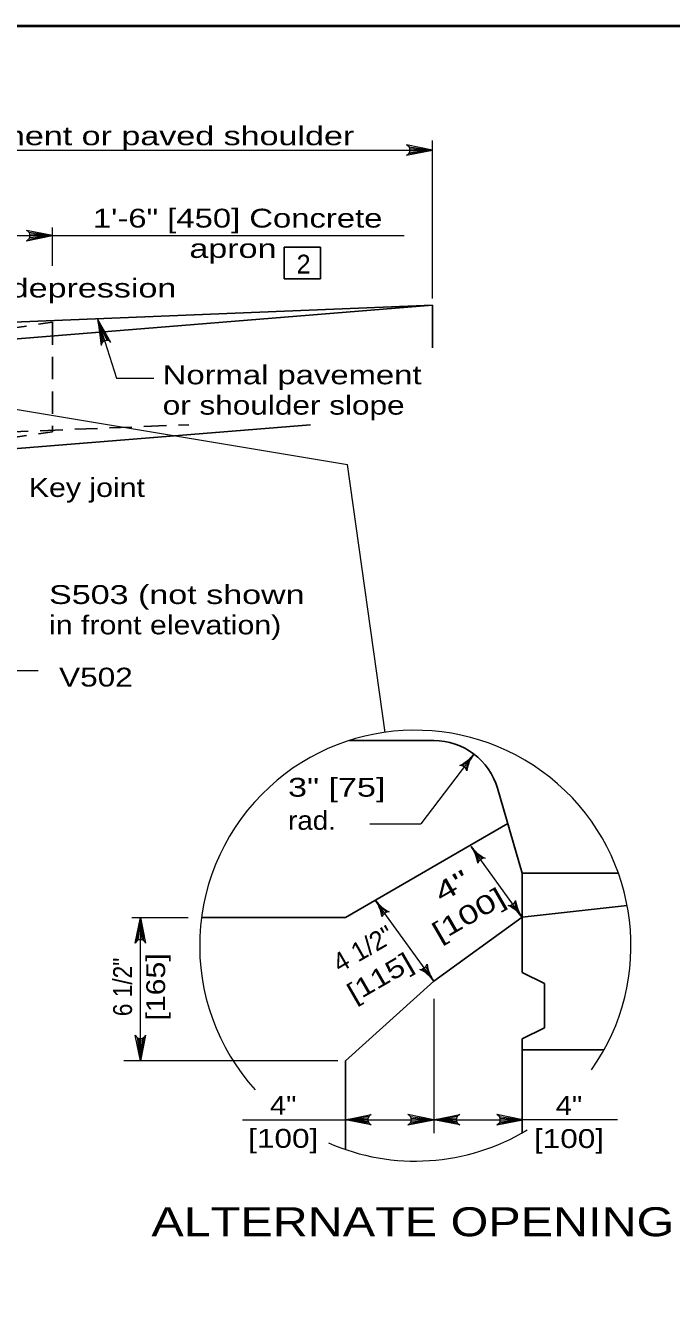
# Model space of a CAD drawing. Extents: x 758.3 to 792.3, y 849.7 to 893.7.
# Drawn here: x 770.01 to 775.35, y 860.56 to 871.19 of the extents above; entities that cross this region are included whole.
import ezdxf
from ezdxf.enums import TextEntityAlignment as Align

# ---------------------------------------------------------------- set-up
doc = ezdxf.new("R2010")
doc.units = 0
doc.header["$LTSCALE"] = 0.062
doc.linetypes.add('MEDIUM_DASHED', pattern=[4.5, 3, -1.5])
doc.layers.add('1', color=7, linetype='Continuous', lineweight=13)

msp = doc.modelspace()

# ---------------------------------------------------------------- linework, layer by layer
at = {"layer": '1', "lineweight": 25}
for p, q in [((760.3205, 871.18817), (791.8205, 871.18817)), ((768.41517, 868.47117), (773.37233, 868.87425)), ((768.6345, 868.68158), (773.37233, 868.87425)), ((773.37233, 868.87425), (773.37233, 868.52192)), ((768.41517, 867.56425), (772.36417, 867.88542)), ((772.6855, 865.271), (773.38417, 865.271)), ((774.11583, 864.17358), (773.911, 864.87592)), ((772.65242, 863.80775), (773.9965, 864.58367)), ((774.98375, 863.90433), (774.11583, 863.80792)), ((771.46317, 863.80775), (772.65242, 863.80775)), ((774.11583, 863.35067), (774.29875, 863.25917)), ((774.29875, 862.89333), (774.29875, 863.25917)), ((774.11583, 862.80192), (774.29875, 862.89333)), ((774.11583, 862.02475), (774.11583, 862.80192)), ((774.79217, 862.7105), (774.11517, 862.7105)), ((772.65242, 861.88642), (772.65242, 862.61875))]:
    msp.add_line(p, q, dxfattribs=at)
at = {"layer": '1'}
for p, q in [((773.37233, 868.92917), (773.37233, 870.23767)), ((768.41517, 870.159), (773.37233, 870.159)), ((773.17608, 870.129), (773.37233, 870.159)), ((773.17842, 870.18608), (773.37233, 870.159)), ((773.1835, 870.14158), (773.37233, 870.159)), ((773.185, 870.17267), (773.37233, 870.159)), ((773.187, 870.159), (773.37233, 870.159)), ((768.41517, 869.451), (773.1385, 869.451)), ((770.03317, 869.421), (770.22933, 869.451)), ((770.03542, 869.47808), (770.22933, 869.451)), ((770.04058, 869.43358), (770.22933, 869.451)), ((770.042, 869.46467), (770.22933, 869.451)), ((770.044, 869.451), (770.22933, 869.451)), ((770.22933, 869.19967), (770.22933, 869.51842)), ((770.66417, 868.58058), (770.60517, 868.75625)), ((770.68183, 868.58292), (770.60517, 868.75625)), ((770.69608, 868.57983), (770.60517, 868.75625)), ((770.65183, 868.57433), (770.60517, 868.75625)), ((770.64125, 868.56383), (770.60517, 868.75625)), ((768.71325, 868.21517), (772.67008, 867.555)), ((772.9825, 865.33825), (772.67008, 867.555)), ((769.69142, 865.85208), (770.11175, 865.85208)), ((773.71558, 865.15958), (773.27658, 864.58075)), ((772.85533, 864.58075), (773.27658, 864.58075)), ((774.11583, 863.80792), (773.69208, 864.39492)), ((773.38417, 863.27983), (772.89992, 863.95067)), ((770.88533, 863.80775), (771.35192, 863.80775)), ((770.92783, 863.61158), (770.95775, 863.80775)), ((770.94033, 863.619), (770.95775, 863.80775)), ((770.95775, 862.61875), (770.95775, 863.80775)), ((770.95775, 863.62242), (770.95775, 863.80775)), ((770.9715, 863.62042), (770.95775, 863.80775)), ((770.98492, 863.61392), (770.95775, 863.80775)), ((773.38417, 863.13433), (773.38417, 862.02175)), ((770.93067, 862.81267), (770.95775, 862.61875)), ((770.94408, 862.80608), (770.95775, 862.61875)), ((770.98775, 862.81492), (770.95775, 862.61875)), ((770.97517, 862.8075), (770.95775, 862.61875)), ((770.95775, 862.80408), (770.95775, 862.61875)), ((772.591, 862.61875), (770.8205, 862.61875)), ((771.803, 862.13292), (773.16875, 862.13292)), ((772.84633, 862.16008), (772.65242, 862.13292)), ((772.83975, 862.14667), (772.65242, 862.13292)), ((772.83775, 862.13292), (772.65242, 862.13292)), ((772.84117, 862.1155), (772.65242, 862.13292)), ((772.84867, 862.10292), (772.65242, 862.13292)), ((773.188, 862.10292), (773.38417, 862.13292)), ((773.19025, 862.16008), (773.38417, 862.13292)), ((773.19542, 862.1155), (773.38417, 862.13292)), ((773.19683, 862.14667), (773.38417, 862.13292)), ((773.19883, 862.13292), (773.38417, 862.13292)), ((773.57808, 862.16008), (773.38417, 862.13292)), ((773.5715, 862.14667), (773.38417, 862.13292)), ((773.5695, 862.13292), (773.38417, 862.13292)), ((773.57292, 862.1155), (773.38417, 862.13292)), ((773.58033, 862.10292), (773.38417, 862.13292)), ((773.92325, 862.10292), (774.11942, 862.13292)), ((773.9255, 862.16008), (774.11942, 862.13292)), ((773.93067, 862.1155), (774.11942, 862.13292)), ((773.93208, 862.14667), (774.11942, 862.13292)), ((773.93408, 862.13292), (774.11942, 862.13292)), ((774.90317, 862.13292), (774.11942, 862.13292))]:
    msp.add_line(p, q, dxfattribs=at)
at = {"layer": '1', "linetype": 'MEDIUM_DASHED', "lineweight": 25}
for p, q in [((768.41517, 868.47117), (770.22933, 868.73317)), ((770.22933, 868.73317), (770.22933, 867.82625)), ((768.41517, 867.76575), (771.35858, 867.88542)), ((768.41517, 867.56425), (770.22933, 867.82625))]:
    msp.add_line(p, q, dxfattribs=at)
at = {"layer": '1', "lineweight": 40}
msp.add_lwpolyline([(760.3205, 871.18817), (791.8205, 871.18817), (791.8205, 850.18817), (760.3205, 850.18817)], close=True, dxfattribs=at)
at = {"layer": '1'}
for points in [[(773.15817, 870.11617), (773.37233, 870.159), (773.15817, 870.20183)], [(770.01517, 869.40817), (770.22933, 869.451), (770.01517, 869.49383)], [(770.714, 868.56692), (770.60517, 868.75625), (770.63275, 868.53958)], [(770.60517, 868.75625), (770.76075, 868.27), (771.0685, 868.27)], [(770.91492, 863.59358), (770.95775, 863.80775), (771.00058, 863.59358)], [(771.00058, 862.83292), (770.95775, 862.61875), (770.91492, 862.83292)], [(772.86658, 862.09008), (772.65242, 862.13292), (772.86658, 862.17575)], [(773.16875, 862.13292), (773.38417, 862.13292), (774.11583, 862.13292)], [(773.17, 862.09008), (773.38417, 862.13292), (773.17, 862.17575)], [(773.59833, 862.09008), (773.38417, 862.13292), (773.59833, 862.17575)], [(773.90525, 862.09008), (774.11942, 862.13292), (773.90525, 862.17575)]]:
    msp.add_lwpolyline(points, dxfattribs=at)
at = {"layer": '1', "lineweight": 25}
msp.add_lwpolyline([(772.14717, 869.35475), (772.14717, 869.093), (772.44575, 869.093), (772.44575, 869.35475)], close=True, dxfattribs=at)
for points in [[(774.11583, 863.35067), (774.11583, 864.17358), (774.91067, 864.17358)], [(774.11583, 863.80792), (773.38417, 863.27983), (772.65242, 862.61875)]]:
    msp.add_lwpolyline(points, dxfattribs=at)
at = {"layer": '1'}
for centre, start, end in [((773.14083, 870.15902), 292.08605, 67.91218), ((769.99787, 869.45103), 292.08605, 67.91218), ((770.67885, 868.53683), 40.65456, 176.48069), ((770.95783, 863.57631), 22.08782, 157.91395), ((770.95774, 862.85022), 202.08782, 337.91395), ((772.88392, 862.13297), 112.08782, 247.91395), ((773.15269, 862.13297), 292.08605, 67.91218), ((773.61562, 862.13297), 112.08782, 247.91395), ((773.88793, 862.13297), 292.08605, 67.91218)]:
    msp.add_arc(centre, 0.04623, start, end, dxfattribs=at)
for centre, major_axis, ratio, start_param, end_param in [((773.23122, 863.57323), (1.78353, 0), 0.999895, 5.66940401, 8.59713226), ((773.45899, 865.35832), (0.32471, 0), 0.999895, 5.15498111, 5.62381242), ((773.58833, 865.2601), (0.20163, 0.25449), 0.500117, 4.27696671, 4.7128289), ((773.84704, 865.06393), (-0.1907, -0.26277), 0.500121, 4.70982398, 5.14829141), ((773.97076, 864.96867), (-0.31868, 0), 0.999895, 5.6407634, 6.11911999), ((773.5981, 865.00444), (-0.06049, 0), 0.999895, 3.41408403, 4.71307422), ((773.23122, 863.57323), (1.78353, 0), 0.999895, 2.31394705, 3.09878016), ((773.822, 864.49261), (-0.19557, 0.25917), 0.500119, 1.56809713, 2.00656456), ((773.94927, 864.58306), (-0.31868, 0), 0.999895, 0.63163034, 1.10998693), ((773.42697, 864.20764), (0.32471, 0), 0.999895, 0.14584805, 0.61467936), ((773.55873, 864.30259), (-0.18445, 0.26719), 0.500123, 4.27683276, 4.71269495), ((773.8061, 864.23718), (-0.06049, 0), 0.999895, 4.68813632, 5.98712651), ((773.02981, 864.04839), (0.19556, -0.25918), 0.500119, 4.70968978, 5.14815721), ((773.15709, 864.13883), (-0.31868, 0), 0.999895, 0.63158302, 1.10993962), ((772.63477, 863.76343), (0.32471, 0), 0.999895, 0.14580073, 0.61463205), ((772.76653, 863.85838), (-0.18444, 0.2672), 0.500123, 4.27683276, 4.71269495), ((774.00184, 863.96563), (0.06049, 0), 0.999895, 4.68813622, 5.98712642), ((774.24921, 863.90022), (0.18445, -0.26719), 0.500123, 4.27683276, 4.71269495), ((774.38096, 863.99517), (-0.32471, 0), 0.999895, 0.1458481, 0.61467941), ((773.0139, 863.79296), (-0.06049, 0), 0.999895, 4.68808891, 5.9870791), ((773.85866, 863.61975), (0.31868, 0), 0.999895, 0.63163034, 1.10998693), ((773.98594, 863.7102), (0.19557, -0.25917), 0.500119, 1.56809713, 2.00656456), ((773.23122, 863.57323), (1.78353, 0), 0.999895, 3.09878118, 3.87453364), ((773.27014, 863.43752), (0.06049, 0), 0.999895, 4.68808891, 5.9870791), ((773.51751, 863.3721), (0.18444, -0.2672), 0.500123, 4.27683276, 4.71269495), ((773.64927, 863.46704), (-0.32471, 0), 0.999895, 0.14580073, 0.61463205), ((773.12695, 863.09165), (0.31868, 0), 0.999895, 0.63158302, 1.10993962), ((773.25423, 863.18209), (-0.19556, 0.25918), 0.500119, 4.70968978, 5.14815721), ((773.23122, 863.57323), (1.78353, 0), 0.999895, 4.29826525, 5.25687552)]:
    msp.add_ellipse(centre, major_axis=major_axis, ratio=ratio, start_param=start_param, end_param=end_param, dxfattribs=at)
at = {"layer": '1', "lineweight": 25}
msp.add_ellipse((773.38415, 864.72225), major_axis=(0.54878, 0), ratio=0.999895, start_param=0.28379403, end_param=1.57079623, dxfattribs=at)

# ---------------------------------------------------------------- texts
at = {"layer": '1'}
for s, height, width, p in [('Pavement or paved shoulder', 0.156, 1.35, (770.92575, 870.1985)), ('1\'-6" [450] Concrete', 0.156, 1.3, (771.76162, 869.51692)), ('apron ', 0.156, 1.35, (771.76175, 869.26575)), ('4"', 0.156, 1.15, (772.13871, 862.17408)), ('4"', 0.156, 1.15, (774.50229, 862.1725)), ('[100]', 0.156, 1.25, (772.13879, 861.90008)), ('[100]', 0.156, 1.25, (774.50237, 861.8985)), ('ALTERNATE OPENING', 0.24, 1.25, (773.21079, 861.16792))]:
    msp.add_text(s, height=height, dxfattribs=dict(at, width=width)).set_placement(p, align=Align.CENTER)
msp.add_text('2', height=0.156, dxfattribs=at).set_placement((772.24908, 869.1365))
for s, width, p in [('2" [50] depression', 1.35, (768.99408, 868.93825)), ('Normal pavement', 1.3, (771.14208, 868.21975)), ('or shoulder slope', 1.25, (771.14208, 867.96858)), ('Key joint', 1.2, (770.03483, 867.28717)), ('S503 (not shown', 1.35, (770.20192, 866.40125)), ('in front elevation)', 1.2, (770.20192, 866.15008)), ('V502', 1.25, (770.28525, 865.71792)), ('3" [75]', 1.35, (772.17892, 864.80625)), ('rad.', 1.1, (772.17892, 864.53225))]:
    msp.add_text(s, height=0.156, dxfattribs=dict(at, width=width)).set_placement(p)
for s, rotation, width, p in [('4"', 29.997, 1.55, (773.57321, 864.0013)), ('[100]', 29.997, 1.4, (773.71013, 863.76394)), ('[115]', 29.997, 1.25, (772.97634, 863.24333)), ('6 1/2"', 90, 0.9, (770.88783, 863.23158)), ('[165]', 90, 1.2, (771.16183, 863.23171))]:
    msp.add_text(s, height=0.156, rotation=rotation, dxfattribs=dict(at, width=width)).set_placement(p, align=Align.CENTER)
msp.add_text('4 1/2"', height=0.156, rotation=29.997, dxfattribs=at).set_placement((772.83942, 863.48067), align=Align.CENTER)

doc.saveas('drawing.dxf')
